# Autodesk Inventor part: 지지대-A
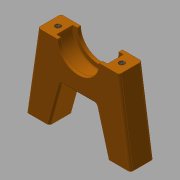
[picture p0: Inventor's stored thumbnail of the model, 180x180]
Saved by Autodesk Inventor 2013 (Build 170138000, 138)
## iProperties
Created: 2018-01
Part Number: 지지대-A
Material: 일반
Document SubType Name: Modeling
Designer: mduedu
Density: 1 g/cm^3
Author: mduedu
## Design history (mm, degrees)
sketch "스케치1"
  geometry: L1 (-22.5, 0)-(22.5, 0); L2 (22.5, 0)-(17.5, 34); L3 (17.5, 34)-(-17.5, 34); L4 (-17.5, 34)-(-22.5, 0); 3 further points
  constraints: 8 end point, 2 midpoint, 1 coincident, 1 horizontal, 1 parallel, 1 vertical alignment
  dimensions: "d0" = 45 distance of L1.start L1.end; "d3" = 35 distance of L2.end L3.end; "d4" = 34 vertical distance of L1.end L2.end
extrude "돌출1" new body sketch "스케치1" stored distance "d5" = 10; taper "d6" = 0 deg
sketch "스케치2"
  geometry: L1 (-12.5, 0)-(12.5, 0); L2 (12.5, 0)-(7.5, 18); L3 (7.5, 18)-(-7.5, 18); L4 (-7.5, 18)-(-12.5, 0); L5 (-22.5, 0)-(22.5, 0) reference; 4 further points
  constraints: 8 end point, 4 midpoint, 1 horizontal, 1 parallel, 1 vertical alignment
  dimensions: "d7" = 10 distance of L1.start L5.start; "d8" = 10 distance of L1.end L5.end (derived); "d9" = 15 distance of L2.end L3.end; "d10" = 18 distance between parallel lines of L1 L3
extrude "돌출2" cut sketch "스케치2" stored distance "d11" = 10; taper "d12" = 0 deg
sketch "스케치3"
  geometry: L1 (-17.5, 34)-(17.5, 34) reference; C1 r 11 at (0, 34); C2 r 9 at (0, 34); 1 further point
  constraints: 2 centre point, 1 coincident, 1 midpoint
  dimensions: "d13" = 22 diameter of C1; "d16" = 18 diameter of C2
extrude "돌출3" cut sketch "스케치3" stored distance "d14" = 7; taper "d15" = 0 deg
extrude "돌출4" cut sketch "스케치3" stored distance "d17" = 7; taper "d18" = 0 deg
fillet "모깎기1" dims "d19" = 0.3
fillet "모깎기2" dims "d20" = 1
fillet "모깎기3" dims "d21" = 1
fillet "모깎기4" dims "d22" = 1
sketch "스케치4"
  geometry: 2 further points
  constraints: 2 other
hole "구멍1" sketch "스케치4" at (-22.771, -3.5), (4.771, -3.5) diameter "d23" = 2.459; stored, may be unused: countersink angle "d27" = 90 deg, drill point angle "d29" = 120 deg; dims "d24" = 4.5, "d25" = 4, "d26" = 2, "d28" = 6
sketch "스케치5"
  geometry: 4 further points
  constraints: 4 other
hole "구멍2" sketch "스케치5" at (40, 4), (5, -27), (40, -27), (5, 4) diameter "d30" = 2.459; stored, may be unused: countersink angle "d34" = 90 deg, drill point angle "d36" = 120 deg; dims "d31" = 6.9, "d32" = 4, "d33" = 2, "d35" = 8.4
node "솔리드1"
